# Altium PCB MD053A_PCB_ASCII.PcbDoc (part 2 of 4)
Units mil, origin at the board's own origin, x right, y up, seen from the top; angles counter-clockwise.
Board outline 3650 x 5180 mil, 4 copper layers (Top Layer, GND Layer, Power Layer, Bottom Layer), stack 58.4 mil thick; 251 components, 138 nets, 532 pads, 1017 vias.
Unrouted connection lines stored in the file: 42.
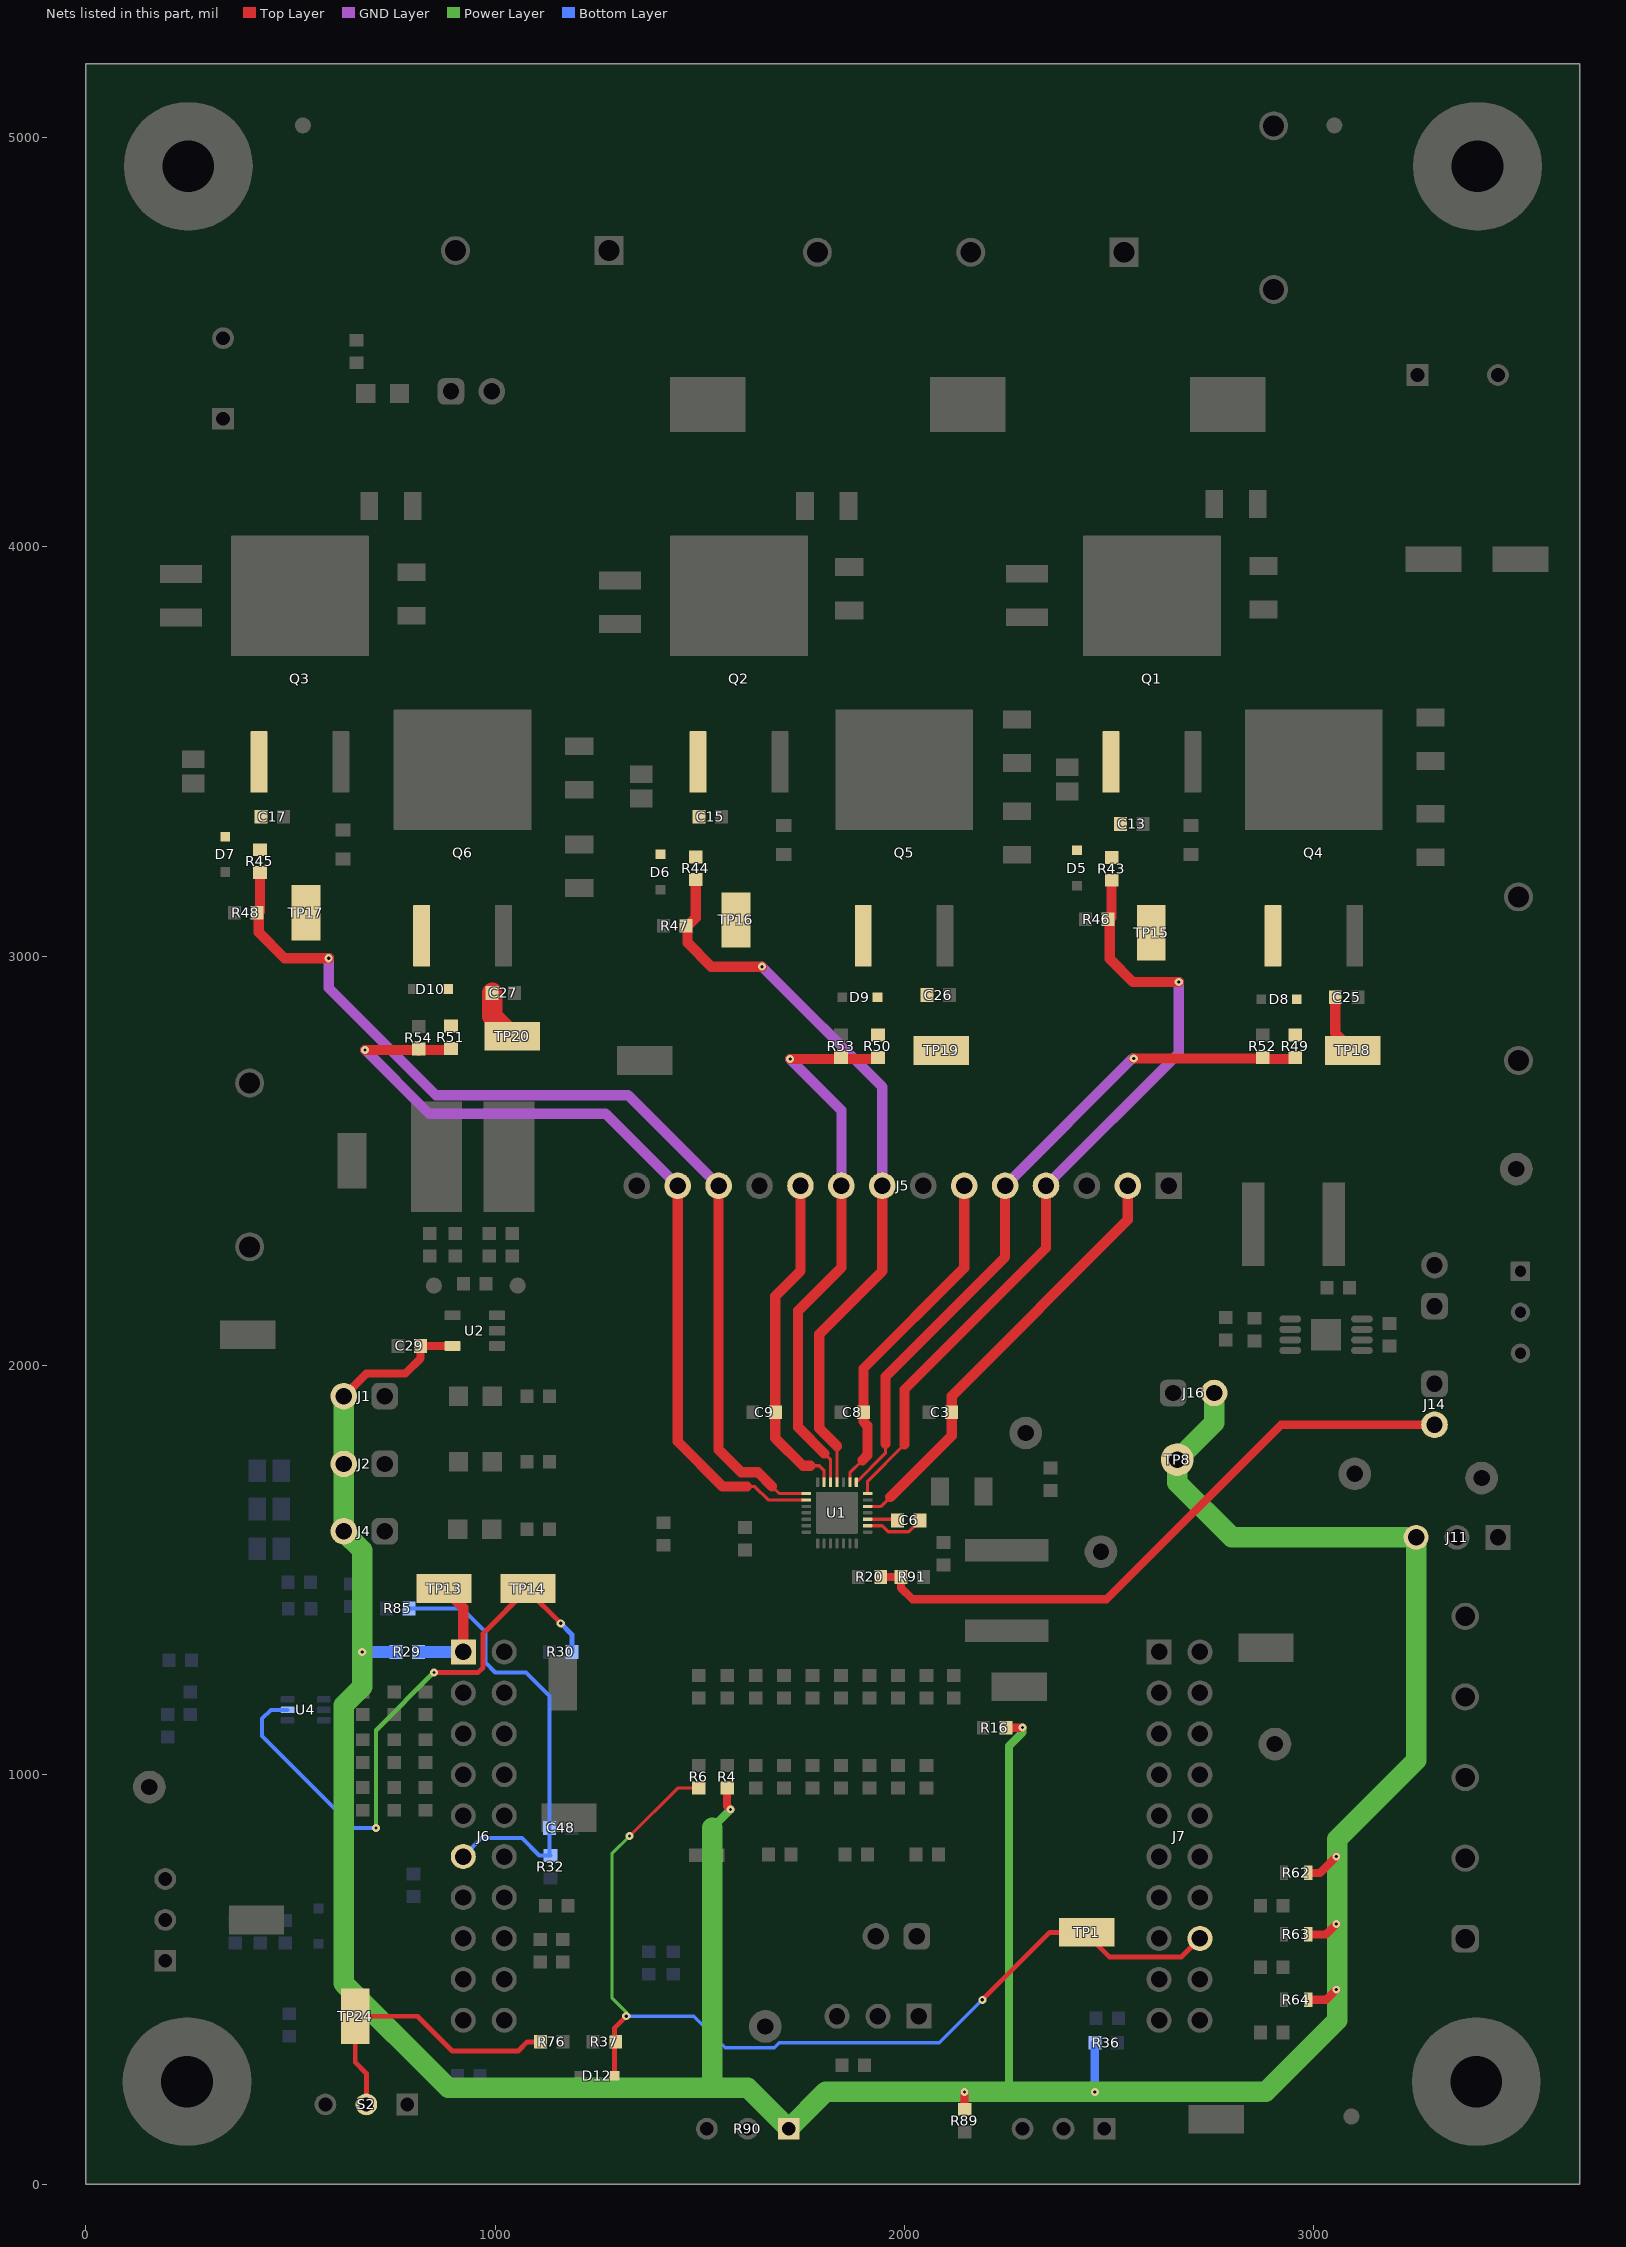
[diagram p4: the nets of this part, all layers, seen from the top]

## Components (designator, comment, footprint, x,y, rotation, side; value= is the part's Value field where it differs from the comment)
C1 "C0603C105K9RACAUTO" 0603L 1610,1577.01 r90 top
C2 "C0603C104K9PAC7867" 0603L 2785,2089.76 r270 top
C3 "C1608X5R1H105K080AB" 0603L 2087.56,1885.43 r180 top
C4 "22201C106MAT2A" 2220_280L 2250,1450 r270 top
C5 "GRM188R72A104KA35J" 0603L 2095,1540 r270 top
C6 "GRM188R71E474KA12D" 0603L 2010,1621.31 r0 top
C7 "UMK316BBJ106KL-T" 1206_190L 2140,1692.43 r0 top
C8 "C1608X5R1H105K080AB" 0603L 1872.16,1885.43 r180 top
C9 "C1608X5R1H105K080AB" 0603L 1656.76,1885.43 r180 top
C10 "12061C392KAZ2A" 1206L 2877.09,3900 r90 top
C11 "12061C392KAZ2A" 1206L 1865,3897.91 r90 top
C12 "12061C392KAZ2A" 1206L 795,3885 r90 top
C13 "GRM188R71H202KA01D" 0603L 2555.16,3323.01 r0 top
C14 "C1210C225K1RACTU" 1210_210L 2299.25,3881.34 r270 top
C15 "GRM188R71H202KA01D" 0603L 1525,3340.67 r0 top
C16 "C1210C225K1RACTU" 1210_210L 1305,3865 r270 top
C17 "GRM188R71H202KA01D" 0603L 454.93,3340.67 r0 top
C18 "C1210C225K1RACTU" 1210_210L 232.32,3880.75 r270 top
C19 "08051C103JAT2A" 0805L 2397.68,3431.97 r270 top
C20 "08051C103JAT2A" 0805L 1356.8,3415 r270 top
C21 "08051C103JAT2A" 0805L 261.85,3451.65 r270 top
C22 "12061C392KAZ2A" 1206L 2275,3525 r270 top
C23 "12061C392KAZ2A" 1206L 1205,3460 r270 top
C24 "12061C392KAZ2A" 1206L 3285,3530 r270 top
C25 "GRM188R71H202KA01D" 0603L 3080,2900 r0 top
C26 "GRM188R71H202KA01D" 0603L 2082.32,2905 r0 top
C27 "GRM188R71H202KA01D" 0603L 1019.72,2910.32 r0 top
C28 "06031C331KAT2A" 0603L 1041.38,2295 r270 top
C29 "C0603C104J4RACTU" 0603L 790,2047.6 r180 top
C30 "C1608NP01H103J080AA" 0603L 950,2200 r180 top
C31 "GRM188R71C222KA01D" 0603L 1110,570 r90 top
C32 "06031C331KAT2A" 0603L 840,2295 r90 top
C33 "22201C106MAT2A" 2220_280L 2950,2345 r180 top
C34 "GRM188R72A104KA35J" 0603L 3060,2190 r180 top
C35 "C0603C106M9PACTU" 0603L 2855,2087.8 r270 top
C36 "GRM188R72A222KA01D" 0603L 425.93,616.22 r270 bottom
C37 "GRM188R71H202KA01D" 0603L 3185,2075 r270 top
C38 "EMZA800ADA100MF80G" CAPSMT_62_F80 3398.7,3970 r0 top
C39 "EKYB101ELL391MK35S" KYB_1250x3500 335,4411.57 r90 top
C40 "EKYB101ELL391MK35S" KYB_1250x3500 3351.57,4420 r0 top
C41 "06035C104JAT2A" 0603L 800,730 r270 bottom
C42 "885012206034" 0603L 2896.85,680 r180 top
C43 "885012206034" 0603L 2896.85,530 r180 top
C44 "885012206034" 0603L 2896.85,370 r180 top
C45 "06035C104JAT2A" 0603L 829.77,1175 r270 top
C46 "06035C104JAT2A" 0603L 829.77,1057.93 r90 top
C47 "06035C104JAT2A" 0603L 829.77,940.86 r90 top
C48 "0603ZC100KAT2A" 0603L 1160,870 r0 bottom
C49 "C0603C105K9RACAUTO" 0603L 1410.85,1588.28 r90 top
D1 "LTST-C170KGKT" LTST-C170KGKT_Green 951.34,1925 r0 top
D2 "LTST-C170KRKT" LED_LTST-C170_Red 951.34,1765 r0 top
D3 "LTST-C170KGKT" LTST-C170KGKT_Green 724.65,4375 r180 top
D4 "LTST-C170KFKT" LTST-C170KFKT_Orange 950,1600 r0 top
D5 "1N4448WX-TP" SOD-323 2421.3,3215.43 r90 top
D6 "1N4448WX-TP" SOD-323 1403.58,3205.59 r90 top
D7 "1N4448WX-TP" SOD-323 340.59,3248.9 r90 top
D8 "1N4448WX-TP" SOD-323 2915,2895 r0 top
D9 "1N4448WX-TP" SOD-323 1890.8,2900 r0 top
D10 "1N4448WX-TP" SOD-323 841.57,2919.83 r0 top
D11 "SZMM3Z3V3ST1G" SOD-323 568.19,630 r90 bottom
D12 "SZMM3Z3V3ST1G" SOD-323 1248.22,264.71 r180 top
FID1 "Fiducial" Fiducial10-20 3050,5030 r0 top
FID2 "Fiducial" Fiducial10-20 530,5030 r0 top
FID3 "Fiducial" Fiducial10-20 3091.85,165 r0 top
H1 "NY PMS 440 0025 PH" "NY PMS 440 0025 PH" 250,4930 r0 top
H2 "NY PMS 440 0025 PH" "NY PMS 440 0025 PH" 3400,4930 r0 top
H3 "NY PMS 440 0025 PH" "NY PMS 440 0025 PH" 3396.85,250 r0 top
H4 "NY PMS 440 0025 PH" "NY PMS 440 0025 PH" 246.85,250 r0 top
H5 "1902C" Keystone_1902C 250.36,4930 r180 bottom
H6 "1902C" Keystone_1902C 3400.36,4930 r180 bottom
H7 "1902C" Keystone_1902C 3396.85,250 r180 bottom
H8 "1902C" Keystone_1902C 246.85,250 r180 bottom
J1 "TSW-102-07-G-S" TSW-102-07-G-S 680,1925 r180 top
J2 "TSW-102-07-G-S" TSW-102-07-G-S 680,1759.41 r180 top
J3 "TSW-102-07-G-S" TSW-102-07-G-S 941.77,4380 r0 top
J4 "TSW-102-07-G-S" TSW-102-07-G-S 680,1595 r180 top
J5 "TSW-114-07-G-S" TSW-114-07-G-S 1995.67,2438.91 r180 top
J6 "SSQ-110-03-G-D" Samtec_SSQ-110-03-x-D 971.85,850 r270 bottom
J7 "SSQ-110-03-G-D" Samtec_SSQ-110-03-x-D 2671.85,850 r270 bottom
J8 "LDO_EN" TSW-102-07-G-S 3295,2195 r90 top
J9 "PVDD_IN" Phoenix_1902547 1090,4846 r180 top
J10 "HALL IN" Phoenix_1792892 3370,993.15 r90 top
J11 "HALL_PWR_SEL" FCI_68001-403HLF 3350,1580 r180 top
J12 "MOTOR_OUT" Phoenix_1904150 2161.8,4842.05 r180 top
J13 "VDS_DISABLE" TSW-102-07-G-S 1980,605 r180 top
J14 "TSW-102-07-G-S" TSW-102-07-G-S 3295,1905 r270 top
J15 "VDSLVL_SEL" FCI_68001-403HLF 1935,410 r180 top
J16 "LDO_OUT" TSW-102-07-G-S 2706.37,1932.76 r0 top
LBL1 "THT-14-423-10" Label_650x200 2403.39,2200.6 r0 top
Logo1 "CE Mark" CE_Mark_5mm 1565.65,613.45 r0 top
Logo2 "Texas Instruments" TI_Stacked_Overlay_Small 1608.01,2198.78 r0 top
Logo3 "FCC disclaimer" FCC_disclaimer 2208,2550 r180 bottom
Logo4 "WEEE logo" WEEE_Minimum 156.74,2140 r0 top
LOGO5 "CAUTION HOT SURFACE" IEC_HotSurface_Small 1075,4120 r0 top
LOGO6 "CAUTION HOT SURFACE" IEC_HotSurface_Small 2065,4092 r0 top
LOGO7 "CAUTION HOT SURFACE" IEC_HotSurface_Small 3076.02,4052 r0 top
NT1 "Net-Tie" NetTie_0603 2700,3283.5 r90 top net-tie
NT2 "Net-Tie" NetTie_0603 1704.76,3284.33 r90 top net-tie
NT3 "Net-Tie" NetTie_0603 627.77,3272.52 r90 top net-tie
Q1 "CSD18536KTTT" KTT0002A-MFG 2604.37,3780 r0 top
Q2 "CSD18536KTTT" KTT0002A-MFG 1595.51,3780 r0 top
Q3 "CSD18536KTTT" KTT0002A-MFG 522.68,3780 r0 top
Q4 "CSD18536KTTT" KTT0002A-MFG 3000,3355 r0 top
Q5 "CSD18536KTTT" KTT0002A-MFG 1999.05,3355 r0 top
Q6 "CSD18536KTTT" KTT0002A-MFG 920,3355.31 r0 top
R1 "ERJ-3GEY0R00V" 0603L 1984.06,995 r90 top
R2 "ERJ-3GEY0R00V" 0603L 1636.11,995 r90 top
R3 "ERJ-3GEY0R00V" 0603L 1844.88,995 r90 top
R4 "ERJ-3GEY0R00V" 0603L 1566.52,995 r90 top
R5 "ERJ-3GEY0R00V" 0603L 1775.29,995 r90 top
R6 "ERJ-3GEY0R00V" 0603L 1496.93,995 r90 top
R7 "ERJ-3GEY0R00V" 0603L 1705.7,995 r90 top
R8 "ERJ-3GEY0R00V" 0603L 1914.47,995 r90 top
R9 "ERJ-3GEY0R00V" 0603L 2120.5,1215 r90 top
R10 "ERJ-3GEY0R00V" 0603L 2053.65,995 r90 top
R11 "ERJ-3GEY0R00V" 0603L 1984.06,1215 r90 top
R12 "ERJ-3GEY0R00V" 0603L 1636.11,1215 r90 top
R13 "ERJ-3GEY0R00V" 0603L 1844.88,1215 r90 top
R14 "ERJ-3GEY0R00V" 0603L 1566.52,1215 r90 top
R15 "ERJ-3GEY0R00V" 0603L 1775.29,1215 r90 top
R16 "CRCW06035K10JNEA" 0603L 2220,1115 r180 top
R17 "ERJ-3GEY0R00V" 0603L 1496.93,1215 r90 top
R18 "ERJ-3GEY0R00V" 0603L 1705.7,1215 r90 top
R19 "ERJ-3GEY0R00V" 0603L 1914.47,1215 r90 top
R20 "ERJ-3GEY0R00V" 0603L 1914.47,1483.21 r180 top
R21 "ERJ-3GEY0R00V" 0603L 2053.65,1215 r90 top
R22 "RC0603JR-07820RL" 0603L 1105,1925 r180 top
R23 "RC0603JR-07820RL" 0603L 1105,1765 r180 top
R24 "RG1608P-202-B-T5" 0603L 661,4477.44 r270 top
R25 "RC0603JR-07820RL" 0603L 1105,1600 r180 top
R26 "ERJ-3GEY0R00V" 0603L 1695.51,805 r0 top
R27 "ERJ-3GEY0R00V" 0603L 1516.93,803.25 r180 top
R28 "ERJ-3GEY0R00V" 0603L 1874.75,290 r0 top
R29 "ERJ-3GEY0R00V" 0603L 785,1300 r0 bottom
R30 "ERJ-3GEY0R00V" 0603L 1160,1300 r0 bottom
R31 "ERJ-3GEY0R00V" 0603L 2055.25,805.11 r0 top
R32 "ERJ-3GEY0R00V" 0603L 1135,775 r90 bottom
R33 "ERJ-3GEY0R00V" 0603L 1881.82,805.11 r180 top
R34 "ERJ-3GEY0R00V" 0603L 1435,540 r90 bottom
R35 "ERJ-3GEY0R00V" 0603L 1150,680 r180 top
R36 "ERJ-3GEY0R00V" 0603L 2493.27,345 r0 bottom
R37 "CRCW060310K0JNEA" 0603L 1266.81,347.4 r180 top
R38 "ERJ-3GEY0R00V" 0603L 2495,405 r0 bottom
R39 "ERJ-3GEY0R00V" 0603L 1375,540 r90 bottom
R40 "CRCW12061R50FKEA" 1206L 2810,4105 r0 top
R41 "CRCW12061R50FKEA" 1206L 1810,4100 r0 top
R42 "CRCW12061R50FKEA" 1206L 745,4100 r0 top
R43 "CRCW060310R0JNEA" 0603L 2505.94,3213.19 r90 top
R44 "CRCW060310R0JNEA" 0603L 1490,3215 r90 top
R45 "CRCW060310R0JNEA" 0603L 425,3232.52 r90 top
R46 "CRCW060310R0JNEA" 0603L 2470,3090 r180 top
R47 "CRCW060310R0JNEA" 0603L 1438.45,3074.13 r180 top
R48 "CRCW060310R0JNEA" 0603L 390.42,3106.39 r180 top
R49 "CRCW060310R0JNEA" 0603L 2955,2780 r90 top
R50 "CRCW060310R0JNEA" 0603L 1935,2780 r90 top
R51 "CRCW060310R0JNEA" 0603L 891.77,2802.05 r90 top
R52 "CRCW060310R0JNEA" 0603L 2875,2780 r90 top
R53 "CRCW060310R0JNEA" 0603L 1845,2780 r90 top
R54 "CRCW060310R0JNEA" 0603L 813.03,2801.12 r90 top
R55 "CRCW12061R50FKEA" 1206L 3285,3295 r90 top
R56 "CRCW12061R50FKEA" 1206L 2275,3300.88 r90 top
R57 "CRCW12061R50FKEA" 1206L 1205,3220 r90 top
R58 "ERJ-3GEY0R00V" 0603L 985,2295 r90 top
R59 "CRCW060356R0JNEA" 0603L 1165,570 r90 top
R60 "CSS2725FT1L00" CSS2725_001 945,2510 r0 top
R61 "ERJ-3GEY0R00V" 0603L 902.6,2295 r90 top
R62 "TNPW060310K0BEEA" TNPW0603 2956.85,760 r0 top
R63 "TNPW060310K0BEEA" TNPW0603 2956.85,610 r0 top
R64 "TNPW060310K0BEEA" TNPW0603 2956.85,450 r0 top
R65 "CRCW0603110KFKEA" 0603L 230,1280 r180 bottom
R66 "CRCW06034K99FKEA" 0603L 255,1175 r90 bottom
R67 "CRCW0603110KFKEA" 0603L 676.39,1175 r90 top
R68 "CRCW0603110KFKEA" 0603L 676.39,1057.93 r90 top
R69 "CRCW0603110KFKEA" 0603L 676.39,940.86 r90 top
R70 "CRCW06034K99FKEA" 0603L 753.08,1175 r270 top
R71 "CRCW06034K99FKEA" 0603L 753.08,1057.93 r270 top
R72 "CRCW06034K99FKEA" 0603L 753.08,940.86 r270 top
R73 "ERA-3ARW103V" 0603L 200,1120 r90 bottom
R74 "ERA-3ARW103V" 0603L 935,264.71 r0 bottom
R75 "ERJ-3GEY0R00V" 0603L 486.85,616.22 r270 bottom
R76 "ERJ-3GEY0R00V" 0603L 1138.27,347.4 r0 top
R77 "ERA-3ARW103V" 0603L 365,616.22 r90 bottom
R78 "RP73PF2A1K0BTDF" 0805L 447.85,1552.3 r0 bottom
R80 "ERJ-3GEY0R00V" 0603L 496.85,388.5 r270 bottom
R81 "ERJ-3GEY0R00V" 0603L 521.14,1470 r0 bottom
R82 "RP73PF2A1K0BTDF" 0805L 447.85,1649.36 r0 bottom
R83 "CRCW0603110KFKEA" 0603L 646.85,1438.24 r90 bottom
R84 "RP73PF2A1K0BTDF" 0805L 447.85,1742.3 r0 bottom
R85 "ERJ-3GEY0R00V" 0603L 761.85,1406.31 r0 bottom
R86 "CRCW06034K99FKEA" 0603L 521.85,1405.72 r0 bottom
R87 "CRCW0603100KJNEA" 0603L 2356.76,1721.91 r270 top
R88 "3296W-1-504LF" FP-3296W-1-504LF_PTH_Potentiometer_9MM53_4MM83-MFG 3505,2130 r90 top
R89 "RC0603JR-077K5L" 0603L 2146.85,155 r90 top
R90 "3352T-1-253LF" Bourns_3352T 1616.93,135 r180 top
R91 "CRCW060310K0JNEA" 0603L 2019.06,1483.21 r180 top
R92 "3352T-1-253LF" Bourns_3352T 2388.35,135 r180 top
S1 "nSLEEP_SW" SW_B12AP 154.33,645.28 r180 top
S2 "DRVOFF_SW" SW_B12AP 685,155 r270 top
SH-J1 "SNT-100-BK-G" SNT-100-BK-G 680,1925 r180 top
SH-J2 "SNT-100-BK-G" SNT-100-BK-G 682,1759.41 r180 top
SH-J3 "SNT-100-BK-G" SNT-100-BK-G 941,4380 r180 top
SH-J4 "SNT-100-BK-G" SNT-100-BK-G 680,1595 r180 top
SH-J5 "SNT-100-BK-G" SNT-100-BK-G 3295,2195 r90 top
SH-J6 "SNT-100-BK-G" SNT-100-BK-G 3292.4,1585 r180 top
SH-J7 "SNT-100-BK-G" SNT-100-BK-G 3295,1905 r90 top
SH-J8 "SNT-100-BK-G" SNT-100-BK-G 1990.84,411.73 r180 top
SH-J9 "SNT-100-BK-G" SNT-100-BK-G 2705,1930 r180 top
TP1 "DRVOFF" Testpoint_Keystone_Miniature 2445,615 r0 top
TP2 "nSLEEP" Testpoint_Keystone_Miniature 1180,895 r0 top
TP3 "LSS" Testpoint_Keystone_Miniature 1365,2745 r0 top
TP4 "nFAULT" Testpoint_Keystone_Miniature 2280,1215 r0 top
TP5 "GND" Testpoint_Keystone_Miniature 1165,1225 r90 top
TP6 "GND" Testpoint_Keystone_Miniature 2761.44,158.56 r180 top
TP7 "GND" Testpoint_Keystone_Miniature 2883.09,1310 r0 top
TP8 "AVDD" Keystone5000 2666.44,1770 r90 top
TP9 "GND" Testpoint_Keystone_Miniature 395,2075 r180 top
TP10 "GND" Testpoint_Keystone_Miniature 650,2500 r90 top
TP11 "PVDD" Keystone5000 2480,1545 r90 top
TP12 "GVDD" Keystone5000 2296.09,1835 r90 top
TP13 "3V3_MCU" Testpoint_Keystone_Miniature 875,1455 r180 top
TP14 "5V" Testpoint_Keystone_Miniature 1080,1455 r0 top
TP15 "GHA_FET" Testpoint_Keystone_Miniature 2602.4,3057.01 r270 top
TP16 "GHB_FET" Testpoint_Keystone_Miniature 1588.09,3088.66 r90 top
TP17 "GHC_FET" Testpoint_Keystone_Miniature 537.44,3106.39 r270 top
TP18 "GLA_FET" Testpoint_Keystone_Miniature 3095,2769.62 r0 top
TP19 "GLB_FET" Testpoint_Keystone_Miniature 2090,2769.62 r180 top
TP20 "GLC_FET" Testpoint_Keystone_Miniature 1041.38,2804.02 r180 top
TP21 "HALL_PWR" Keystone5000 3100,1735 r90 top
TP22 "GND" Keystone5001 2905,1075 r90 top
TP23 "nSLEEP_SW" Testpoint_Keystone_Miniature 416.85,645 r0 top
TP24 "INHA" Testpoint_Keystone_Miniature 657.85,410 r90 top
TP25 "GND" Harwin_D3082-05 3500,2945 r90 top
TP26 "GND" Harwin_D3082-05 400,2490 r270 top
TP27 "GND" Harwin_D3082-05 2902,4829 r90 top
TP28 "GND" Keystone5001 3495,2480 r90 top
TP29 "GND" Keystone5001 155,970 r90 top
TP30 "EXT_VDSLVL" Keystone5000 1660,385 r90 top
TP31 "EXT_HALL_PWR" Keystone5000 3410,1725 r90 top
TP32 "SP" TP_SM_1MM 1054.88,2195 r90 top
TP33 "SN" TP_SM_1MM 850,2195 r90 top
TP34 "OUTA" Testpoint_Keystone_Compact 2790,4347.89 r0 top
TP35 "OUTA" Testpoint_Keystone_Compact 2154.56,4347.89 r0 top
TP36 "OUTA" Testpoint_Keystone_Compact 1519.12,4347.89 r0 top
U1 "DRV8328ARUYR" RUY0028A-MFG 1835,1640 r180 top
U2 "INA180A1IDBVR" DBV0005A_N 950,2085 r180 top
U3 "TPS7A1633QDGNRQ1" DGN0008B_N 3030,2075 r0 top
U4 "TPD4S009DCKR" DCK0006A_N 536.85,1158.5 r180 bottom
ZZ1 "This Assembly Note is for PCB labels only" AssemblyNoteLabel 4947.75,2616.47 r90 top
ZZ2 "These assemblies are ESD sensitive, ESD precautions shall be observed." AssemblyNote 4770.59,5096.77 r90 top
ZZ3 "These assemblies must be clean and free from flux and all contaminants. Use of no clean flux is not acceptable." AssemblyNote 4593.42,3551.5 r90 top
ZZ4 "These assemblies must comply with workmanship standards IPC-A-610 Class 2, unless otherwise specified." AssemblyNote 4416.26,3876.31 r90 top

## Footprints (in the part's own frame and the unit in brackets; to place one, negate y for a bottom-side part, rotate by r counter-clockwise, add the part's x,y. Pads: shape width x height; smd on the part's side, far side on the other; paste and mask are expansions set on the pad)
0603L [mm] "0603 from SM-752 data"
  rect 0.8x0.85 smd: 1(-0.7,0) 2(0.7,0)
  silkscreen extent -0.07,-0.33 0.07,0.33
0805L [mm] "0805 from SM-752 data"
  rect 1.1x1.4 smd: 1(-0.75,0) 2(0.75,0)
1206_190L [mm] "1206_190"
  rect 1.1x1.75 smd: 1(-1.35,0) 2(1.35,0)
  silkscreen extent -0.4,-0.77 0.4,0.77
1206L [mm] "1206 from SM-752 data"
  rect 1.1x1.75 smd: 1(-1.35,0) 2(1.35,0)
  silkscreen extent -0.4,-0.77 0.4,0.77
1210_210L [mm] "1210"
  rect 1.1x2.6 smd: 1(-1.35,0) 2(1.35,0)
  silkscreen extent -0.4,-1.2 0.4,1.2
2220_280L [mm] "Chip Capacitor, Body 5.7x5.0mm, IPC High Density"
  rect 1.4x5.2 smd: 1(-2.5,0) 2(2.5,0)
  silkscreen extent -1.4,-2.5 1.4,2.5
AssemblyNote [mil] "Assembly Note"
AssemblyNoteLabel [mil] "Assembly Note for PCB Labels"
Bourns_3352T [mm] "TH, 3-Leads, Body 9.53x8.89mm, Pitch 2.54mm"
  rect 1.35x1.35 hole 0.85: 1(-2.54,0)
  round 1.35 hole 0.85: 2(0,0) 3(2.54,0)
  silkscreen extent -4.44,-2.6 4.44,7.31
CAPSMT_62_F80 [mm] "6.3 x 7.7mm:  Chemi-Con F80"
  rect 3.5x1.6 smd: 1(-2.7,0) 2(2.7,0)
  silkscreen extent -3.36,-3.4 3.44,3.4
CE_Mark_5mm [mil] "Minimum text height for CE Mark"
CSS2725_001 [mm] "STACKPOLE ELECTRONICS"
  rect 3.18x6.86 smd: 1(-2.25,0) 2(2.25,0)
  silkscreen extent -4.13,-3.7 4.13,3.7
DBV0005A_N [mm] "SOT23, 5-Leads, Body 2.9x1.6mm, Pitch 0.95mm, Lead Span 2.8mm, IPC Medium Density"
  rrect17% 1x0.6 smd: 1(-1.375,0.95) 2(-1.375,0) 3(-1.375,-0.95) 4(1.375,-0.95) 5(1.375,0.95)
  silkscreen extent -0.25,-1.55 0.25,1.55
DCK0006A_N [mm] "SOT23, 6-Leads, Body 2x1.3mm, Pitch 0.65mm, Lead Span 2.1mm, IPC Medium Density"
  rrect25% 0.85x0.4 smd: 1(-1.125,0.65) 2(-1.125,0) 3(-1.125,-0.65) 4(1.125,-0.65) 5(1.125,0) 6(1.125,0.65)
  silkscreen extent -1.5,-1.09 0.51,1.09
DGN0008B_N [mm] "TSOP, 8-Leads, Body 3x3mm, Pitch 0.65mm, Thermal Pad 1.92x1.60mm, IPC Medium Density"
  rrect100% 1.35x0.45 smd: 1(-2.225,0.975) 2(-2.225,0.325) 3(-2.225,-0.325) 4(-2.225,-0.975) 5(2.225,-0.975) 6(2.225,-0.325) 7(2.225,0.325) 8(2.225,0.975)
  rrect5% 1.88x1.98 smd: 9(0,0)
  silkscreen extent -2.7,-1.55 0.95,1.55
FCC_disclaimer [mil]
FCI_68001-403HLF [mm] "Header, 2.54mm, 3x1, TH"
  rect 1.55x1.55 hole 1.02: 1(-2.54,0)
  round 1.55 hole 1.02: 2(0,0) 3(2.54,0)
  silkscreen extent -3.81,-1.21 3.81,1.5
Fiducial10-20 [mm]
  round 1 smd mask+0: 1(0,0)
  Top Layer keep-out circle w1.178: c0,0 r0.5
FP-3296W-1-504LF_PTH_Potentiometer_9MM53_4MM83-MFG [mm]
  rrect8% 1.2x1.2 hole 0.7 paste-1000 mask+0: 1(2.54,0.005)
  round 1.2 hole 0.7 paste-1000 mask+0: 2(0,0.005) 3(-2.54,0.005)
  silkscreen extent -4.89,-2.48 5.77,2.48
Harwin_D3082-05 [mm] "Shorting Plug, 10.16mm spacing, TH"
  round 1.8 hole 1.3: 1(-5.08,0) 2(5.08,0)
  silkscreen extent -3.9,-0.53 3.9,0.53
IEC_HotSurface_Small [mil]
  silkscreen extent -107,-93 107,92
Keystone5000 [mil] "For Keystone 500x miniature loop terminals"
  round 80 hole 40: 1(0,0)
  silkscreen extent -52,-52 52,52
Keystone5001 [mil] "For Keystone 500x miniature loop terminals"
  round 80 hole 40: 1(0,0)
  silkscreen extent -52,-52 52,52
Keystone_1902C [mil] "Hex Standoff, 4-40 threaded, nylon"
  round 1 on Mech4: 0(0,0)
KTT0002A-MFG [mm]
  rrect10% 1.05x3.82 smd paste+0 mask+0: 1(-2.54,-7.755) 3(2.54,-7.755)
  rrect1% 8.55x7.48 smd paste-1000 mask+0: 4(0,2.545)
  silkscreen extent -5.13,-4.62 5.13,4.62
KYB_1250x3500 [mm] "TH, 2-Leads, Dia 12.5mm, Lead Spacing 5mm"
  rect 1.35x1.35 hole 0.85: 1(-2.5,0)
  round 1.35 hole 0.85: 2(2.5,0)
  silkscreen extent -8,-6.5 6.5,6.5
Label_650x200 [mil] "Thermal Transfer Label"
  round 1 on Mech13: 0(0,0)
  silkscreen extent -325,-100 325,100
LED_LTST-C170_Red [mm] "LITE-ON"
  rect 1.2x1.2 smd: 1(-1.05,0) 2(1.05,0)
  silkscreen extent -1.6,-0.99 2.3,1.01
LTST-C170KFKT_Orange [mm] "LITE-ON"
  rect 1.2x1.2 smd: 1(-1.05,0) 2(1.05,0)
  silkscreen extent -1.6,-1.01 2.29,0.99
LTST-C170KGKT_Green [mm] "LITE-ON"
  rect 1.2x1.2 smd: 1(-1.05,0) 2(1.05,0)
  silkscreen extent -1.6,-1.01 2.31,0.99
NetTie_0603 [mm] "Net Tie 0603 size"
  rect 0.8x0.95 smd paste-1: 1(-0.9,0) 2(0.9,0)
  silkscreen extent -0.1,-0.38 0.1,0.38
"NY PMS 440 0025 PH" [mm] "4-40 nylon screw and mounting hole"
  round 8 hole 3.2: 1(0,0)
Phoenix_1792892 [mm] "Terminal Block, 5mm, 5x1, R/A, TH"
  rrect50% 1.7x1.7 hole 1.2: 1(-10,0)
  round 1.7 hole 1.2: 2(-5,0) 3(0,0) 4(5,0) 5(10,0)
  silkscreen extent -12.8,-4.95 12.5,5.55
Phoenix_1902547 [mm] "TH, 2-Leads, Body 19.04x16mm, Pitch 9.52mm"
  rect 1.8x1.8 hole 1.3: 1(-4.76,3.1)
  round 1.8 hole 1.3: 2(4.76,3.1)
  silkscreen extent -10,-8 10.09,8
Phoenix_1904150 [mm] "TH, 3-Leads, Body 28.56x16mm, Pitch 9.52mm"
  rect 1.8x1.8 hole 1.3: 1(-9.52,3.1)
  round 1.8 hole 1.3: 2(0,3.1) 3(9.52,3.1)
  silkscreen extent -14.8,-8 14.85,8
RUY0028A-MFG [mm]
  rrect50% 0.6x0.2 smd paste+0 mask+0: 1(-1.9,1.2) 2(-1.9,0.8) 3(-1.9,0.4) 4(-1.9,0) 5(-1.9,-0.4) 6(-1.9,-0.8) 7(-1.9,-1.2) 15(1.9,-1.2) 16(1.9,-0.8) 17(1.9,-0.4) 18(1.9,0) 19(1.9,0.4) 20(1.9,0.8) 21(1.9,1.2)
  rrect50% 0.2x0.6 smd paste+0 mask+0: 8(-1.2,-1.9) 9(-0.8,-1.9) 10(-0.4,-1.9) 11(0,-1.9) 12(0.4,-1.9) 13(0.8,-1.9) 14(1.2,-1.9) 22(1.2,1.9) 23(0.8,1.9) 24(0.4,1.9) 25(0,1.9) 26(-0.4,1.9) 27(-0.8,1.9) 28(-1.2,1.9)
  rrect5% 2.6x2.6 smd paste-1000 mask+0: 29(0,0)
  silkscreen extent -2.88,-2.05 2.05,2.05
Samtec_SSQ-110-03-x-D [mm] "Receptacle, 2.54mm, 10x2, TH"
  rect 1.55x1.55 hole 1.02: 1(-11.43,1.27)
  round 1.55 hole 1.02: 2(-11.43,-1.27) 3(-8.89,1.27) 4(-8.89,-1.27) 5(-6.35,1.27) 6(-6.35,-1.27) 7(-3.81,1.27) 8(-3.81,-1.27) 9(-1.27,1.27) 10(-1.27,-1.27) 11(1.27,1.27) 12(1.27,-1.27) 13(3.81,1.27) 14(3.81,-1.27) 15(6.35,1.27) 16(6.35,-1.27) 17(8.89,1.27) 18(8.89,-1.27) 19(11.43,1.27) 20(11.43,-1.27)
  silkscreen extent -12.95,-2.48 12.95,3
SNT-100-BK-G [mil] "Samtec STEP model"
  round 1 on Mech3: 0(0,0)
SOD-323 [mm] "NXP recommended land pattern"
  rect 0.6x0.6 smd paste-0.05: 1(-1.1,0) 2(1.1,0)
  silkscreen extent -2.14,-0.86 1.53,0.87
SW_B12AP [mm] "NKK Switches"
  rect 1.35x1.35 hole 0.85 paste+0: 1(-1,2.54)
  round 1.35 hole 0.85 paste+0: 2(-1,0) 3(-1,-2.54)
  silkscreen extent -4.27,-4.4 3.4,4.4
Testpoint_Keystone_Compact [mil] "Compact SMT test point"
  rect 185x135 smd: 1(0,0)
  silkscreen extent -110,-80 110,80
Testpoint_Keystone_Miniature [mil] "Miniature SMT test point"
  rect 135x70 smd: 1(0,0)
  silkscreen extent -78,-46 78,45
TI_Stacked_Overlay_Small [mil]
TNPW0603 [mm] "Vishay"
  rect 0.5x0.9 smd: 1(-0.75,0) 2(0.75,0)
  silkscreen extent -0.2,-0.6 0.2,0.6
TP_SM_1MM [mm] "1mm Test Point, SMT"
  round 1 smd paste-0.5: 1(0,0)
TSW-102-07-G-S [mm] "Samtec 100mil, 1x2, 230 mil above insulator"
  rrect50% 1.65x1.65 hole 1.016: 1(-1.27,0)
  round 1.65 hole 1.016: 2(1.27,0)
  silkscreen extent -2.54,-1.27 2.54,2.12
TSW-114-07-G-S [mm] "Samtec 100mil, 1x14, 230 mil above insulator"
  rrect6% 1.65x1.65 hole 1.016: 1(-16.51,0)
  round 1.65 hole 1.016: 2(-13.97,0) 3(-11.43,0) 4(-8.89,0) 5(-6.35,0) 6(-3.81,0) 7(-1.27,0) 8(1.27,0) 9(3.81,0) 10(6.35,0) 11(8.89,0) 12(11.43,0) 13(13.97,0) 14(16.51,0)
  silkscreen extent -17.78,-1.27 17.78,1.65
WEEE_Minimum [mil] "WEEElie bin"
  silkscreen extent 22,-71 54,74

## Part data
C1 C49: library part CMP-0086190-1, "CAP, CERM, 1 µF, 6.3 V,+/- 10%, X7R, AEC-Q200 Grade 1, 0603"
C2: library part CMP-0085846-1, "CAP, CERM, 0.1 µF, 6.3 V,+/- 10%, X5R, 0603"
C3 C8 C9: library part CMP-0007011-4, "CAP, CERM, 1 uF, 50 V, +/- 10%, X5R, 0603"
C4 C33: library part CMP-0009304-2, "CAP, CERM, 10 uF, 100 V, +/- 20%, X7R, 2220"
C5 C34: library part CMP-0007470-5, "CAP, CERM, 0.1 uF, 100 V, +/- 10%, X7R, 0603"
C6: library part CMP-0007424-3, "CAP, CERM, 0.47 uF, 25 V, +/- 10%, X7R, 0603"
C7: library part CMP-0086153-1, "CAP, CERM, 10 µF, 50 V,+/- 10%, X5R, 1206"
C10 C11 C12 C22 C23 C24: library part CMP-0008756-2, "CAP CER 3900PF 100V X7R 1206"
C13 C15 C17 C25 C26 C27 C37: library part CMP-0007441-5, "CAP, CERM, 2000 pF, 50 V, +/- 10%, X7R, 0603"
C14 C16 C18: library part CMP-0009084-1, "CAP, CERM, 2.2 uF, 100 V, +/- 10%, X7R, 1210"
C19 C20 C21: library part CMP-0007542-2, "CAP, CERM, 0.01 uF, 100 V, +/- 5%, X7R, 0805"
C28 C32: library part CMP-0006740-4, "CAP, CERM, 330 pF, 100 V, +/- 10%, X7R, 0603"
C29: library part CMP-0006857-4, "CAP, CERM, 0.1 uF, 16 V, +/- 5%, X7R, 0603"
C30: library part CMP-0006998-4, "CAP, CERM, 0.01 uF, 50 V, +/- 5%, C0G/NP0, 0603"
C31: library part CMP-0007387-4, "CAP, CERM, 2200 pF, 16 V, +/- 10%, X7R, 0603"
C35: library part CMP-0006872-5, "CAP, CERM, 10 uF, 6.3 V, +/- 20%, X5R, 0603"
C36: library part CMP-0007475-4, "CAP, CERM, 2200 pF, 100 V, +/- 10%, X7R, 0603"
C38: library part CMP-0011397-2, "CAP, AL, 10 uF, 80 V, +/- 20%, 2.4 ohm, SMD"
C39 C40: library part CMP-0009875-2, "CAP, AL, 390 uF, 100 V, +/- 20%, 0.026 ohm, TH"
C41 C45 C46 C47: library part CMP-0083854-1, "CAP, CERM, 0.1 µF, 50 V,+/- 5%, X7R, 0603"
C42 C43 C44: library part CMP-0006826-4, "CAP, CERM, 1000 pF, 16 V, +/- 10%, X7R, 0603"
C48: library part CMP-0006811-4, "CAP, CERM, 10 pF, 10 V, +/- 10%, X7R, 0603"
D1 D3: library part CMP-0002888-2, "LED, Green, SMD"
D2: library part CMP-0002829-3, "LED, Red, SMD"
D4: library part CMP-0002890-1, "LED, Orange, SMD"
D5 D6 D7 D8 D9 D10: library part CMP-0076911-2, "Diode, Switching, 75 V, 0.25 A, SOD-323"
D11 D12: library part CMP-0085730-1, "Diode, Zener, 3.3 V, 300 mW, AEC-Q101, SOD-323"
FID1 FID2 FID3: library part CMP-0077181-1, "Fiducial mark.  There is nothing to buy or mount."
H1 H2 H3 H4: library part CMP-0003617-1, "Machine Screw, Round, #4-40 x 1/4, Nylon, Philips panhead"
H5 H6 H7 H8: library part CMP-0003610-1, "Standoff, Hex, 0.5\"L #4-40 Nylon"
J1 J2 J3 J4 J8 J13 J14 J16: library part CMP-0075405-3, "Header, 100mil, 2x1, Gold, TH"
J5: library part CMP-0075428-1, "Header, 100mil, 14x1, Gold, TH"
J6 J7: library part CMP-0075613-1, "Receptacle, 2.54mm, 10x2, Gold, TH"
J9: library part CMP-0055527-1, "Terminal Block, 9.52mm, 2x1, R/A, TH"
J10: library part CMP-0055532-1, "Terminal Block, 5mm, 5x1, R/A, TH"
J11 J15: library part CMP-0065026-1, "Header, 2.54mm, 3x1, Tin, TH"
J12: library part CMP-0055528-1, "Terminal Block, 9.52mm, 3x1, R/A, TH"
LBL1: library part CMP-0003625-1, "Thermal Transfer Printable Labels, 0.650\" W x 0.200\" H - 10,000 per roll"
Logo1: library part CMP-0074844-1
Logo2: library part CMP-0074838-1, "Texas Instrument Corporate Signature"
Logo3: library part CMP-0074847-1, "FCC_disclaimer"
Logo4: library part CMP-0074769-1
LOGO5 LOGO6 LOGO7: library part CMP-0074837-1, "IEC 61010-1 Hot Surface Warning"
NT1 NT2 NT3: library part CMP-0078142-2, "Single point connection between nets."
Q1 Q2 Q3 Q4 Q5 Q6: library part CMP-0092295-1, "MOSFET 60-V, N channel NexFET power MOSFET, single D2PAK, 1.6 mOhm 3-DDPAK/TO-263 -55 to 175"
R1 R2 R3 R4 R5 R6 R7 R8 R9 R10 R11 R12 R13 R14 R15 R17 R18 R19 R20 R21 R26 R27 R28 R29 R30 R31 R32 R33 R34 R35 R36 R38 R39 R58 R61 R75 R76 R80 R81 R85: library part CMP-0025874-4, "RES, 0, 5%, 0.1 W, AEC-Q200 Grade 0, 0603"
R16: library part CMP-0025830-4, "RES, 5.1 k, 5%, 0.1 W, AEC-Q200 Grade 0, 0603"
R22 R23 R25: library part CMP-0025941-5, "RES, 820, 5%, 0.1 W, 0603"
R24: library part CMP-0023463-3, "RES, 2.00 k, 0.1%, 0.1 W, 0603"
R37: library part CMP-0025701-2, "RES, 10 k, 5%, 0.1 W, 0603"
R40 R41 R42 R55 R56 R57: library part CMP-0016763-3, "RES, 1.50, 1%, 0.25 W, AEC-Q200 Grade 0, 1206"
R43 R44 R45 R46 R47 R48 R49 R50 R51 R52 R53 R54: library part CMP-0025703-4, "RES, 10, 5%, 0.1 W, AEC-Q200 Grade 0, 0603"
R59: library part CMP-0025829-4, "RES, 56, 5%, 0.1 W, AEC-Q200 Grade 0, 0603"
R60: library part CMP-0015025-2, "RES, 0.001, 1%, 4 W, RES_2725"
R62 R63 R64: library part CMP-0025686-1, "RES, 10.0 k, 0.1%, 0.1 W, AEC-Q200 Grade 1, 0603"
R65 R67 R68 R69 R83: library part CMP-0022008-4, "RES, 110 k, 1%, 0.1 W, AEC-Q200 Grade 0, 0603"
R66 R70 R71 R72 R86: library part CMP-0022458-4, "RES, 4.99 k, 1%, 0.1 W, AEC-Q200 Grade 0, 0603"
R73 R74 R77: library part CMP-0086251-1, "RES, 10.0 k, 0.05%, 0.1 W, AEC-Q200 Grade 0, 0603"
R78 R82 R84: library part CMP-0019089-2, "RES, 1.00 k, 0.1%, 0.25 W, 0805"
R87: library part CMP-0025698-4, "RES, 100 k, 5%, 0.1 W, AEC-Q200 Grade 0, 0603"
R88: library part CMP-0088033-1, "500 kOhms 0.5W, 1/2W PC Pins Through Hole Trimmer Potentiometer Cermet 25 Turn Top Adjustment"
R89: library part CMP-0025940-5, "RES, 7.5 k, 5%, 0.1 W, 0603"
R90 R92: library part CMP-0001776-2, "Trimmer Potentiometer, 25kohm, 0.5W, TH"
R91: library part CMP-0025701-3, "RES, 10 k, 5%, 0.1 W, 0603"
S1 S2: library part CMP-0002155-2, "SWITCH TOGGLE SPDT 0.4VA 28V"
SH-J1 SH-J2 SH-J3 SH-J4 SH-J5 SH-J6 SH-J7 SH-J8 SH-J9: library part CMP-0003623-3, "Shunt, 100mil, Gold plated, Black"
TP1 TP2 TP3 TP4 TP5 TP6 TP7 TP9 TP10 TP13 TP14 TP15 TP16 TP17 TP18 TP19 TP20 TP23 TP24: library part CMP-0055152-1, "Test Point, Miniature, SMT"
TP8 TP11 TP12 TP21 TP30 TP31: library part CMP-0055137-1, "Test Point, Miniature, Red, TH"
TP22 TP28 TP29: library part CMP-0055138-1, "Test Point, Miniature, Black, TH"
TP25 TP26 TP27: library part CMP-0075110-1, "1mm Uninsulated Shorting Plug, 10.16mm spacing, TH"
TP32 TP33: library part CMP-0003825-1, "1mm Test Point, SMT"
TP34 TP35 TP36: library part CMP-0055153-1, "Test Point, Compact, SMT"
U1: library part CMP-0091885-1, "Three-Phase BLDC Gate Driver"
U2: library part CMP-0013067-2, "Low- and High-Side Measurement, Multichannel, Voltage Output, Current-Sense Amplifier, DBV0005A (SOT-5)"
U3: library part CMP-0066910-3, "Automotive 60V, 5uA IQ Low-Dropout 100mA Linear Regulator with Enable and Power Good, DGN0008B (VSSOP-8)"
U4: library part CMP-0043118-3, "4-Channel ESD Solution for High-Speed Differential Interface, DCK0006A (SOT-SC70-6)"
ZZ1: library part CMP-0003616-3
ZZ2: library part CMP-0077236-1
ZZ3: library part CMP-0077237-1
ZZ4: library part CMP-0077238-1

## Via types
v1: diameter 20, hole 10, Top Layer to Bottom Layer, tented both sides, 759 vias
v2: diameter 19.68, hole 7.87, Top Layer to Bottom Layer, tented both sides, 248 vias
v3: diameter 19.68, hole 7.87, Top Layer to Bottom Layer, 10 vias

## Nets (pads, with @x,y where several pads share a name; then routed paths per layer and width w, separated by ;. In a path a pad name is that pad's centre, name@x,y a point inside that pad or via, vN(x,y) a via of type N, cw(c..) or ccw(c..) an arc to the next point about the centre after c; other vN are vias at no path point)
3V3_MCU: J6.1 R29.2 TP13.1 | length 283.7
  Top Layer w25: TP13.1@875,1455 921.85,1408.15 J6.1@921.85,1300
  Bottom Layer w30: R29.2@812.56,1300 J6.1@921.85,1300
+5V: R30.2 TP14.1 U4.5 | length 1486.9
  Top Layer w12: v2(850,1250) 958.15,1250 970.24,1262.08 970.24,1345.24 TP14.1@1080,1455 1080,1450 v2(1160,1370)
  Power Layer w10: v2(708.54,870) 708.54,1108.54 710,1110
  Power Layer w12: 710,1110 v2(850,1250)
  Bottom Layer w10: U4.5@492.56,1158.5 451.59,1158.5 430,1136.91 430,1095 655,870 v2(708.54,870)
  Bottom Layer w12: v2(1160,1370) 1187.56,1342.44 R30.2@1187.56,1300
AVDD: C29.1 J1.2 J2.2 J4.2 J11.3 J16.2 R4.1 R16.1 R29.1 R36.1 R62.2 R63.2 R64.2 R89.2 R90.1 TP8.1 U2.5 | length 8830
  Top Layer w20: J1.2@630,1925 685,1980 780,1980 817.56,2017.56 C29.1@817.56,2047.6 U2.5@895.87,2047.6 ; R4.1@1566.52,967.44 1566.52,923.48 v2(1575,915) ; R89.2@2146.85,186.5 v2(2146.85,225) ; R16.1@2247.56,1115 2287.81,1115 v2(2288.35,1115.53) ; R64.2@2986.38,450 3030,450 v2(3055,475) ; R63.2@2986.38,610 3030,610 v2(3055,635) ; R62.2@2986.38,760 3015,760 v2(3055,800)
  Power Layer w20: 985,235 985.12,235 ; 1530,870 v2(1575,915) ; 2255,225 2255,1070 2288.35,1103.35 v2(2288.35,1115.53)
  Power Layer w50: J1.2@630,1925 J2.2@630,1759.41 J4.2@630,1595 630,1593.06 675,1548.06 v2(675,1300) 675,1215 630,1170 630,490 885,235 985,235 ; 985.12,235 1530,235 ; 1530,870 1530,235 ; J16.2@2756.37,1932.76 2756.37,1859.93 TP8.1@2666.44,1770 2666.44,1713.56 2800,1580 J11.3@3250,1580 3250,1035 3057.17,842.17 3057.17,400 2882.17,225 v2(2465,225) 2255,225 v2(2146.85,225) 1806.93,225 R90.1@1716.93,135 1616.93,235 1530,235
  Bottom Layer w20: v2(2465,225) 2465,344.29 R36.1@2465.71,345
  Bottom Layer w30: v2(675,1300) R29.1@757.44,1300
BSTA: C3.1 J5.2 U1.5 | length 1065.8
  Top Layer w7.87: U1.5@1909.8,1655.75 1942.63,1655.75 1965.32,1678.44
  Top Layer w25: 1965.32,1678.44 2115.12,1828.24 C3.1@2115.12,1885.43 2115.12,1925.12 2545.67,2355.67 J5.2@2545.67,2438.91
BSTB: C8.1 J5.6 U1.9 | length 847.7
  Top Layer w7.87: U1.9@1866.5,1714.8 1866.5,1737.78 1897.27,1768.55
  Top Layer w25: 1897.27,1768.55 1909.37,1780.65 1909.37,1853.14 1899.72,1862.8 C8.1@1899.72,1885.43 1899.72,1992.58 2145.67,2238.54 J5.6@2145.67,2438.91
BSTC: C9.1 J5.10 U1.13 | length 821.7
  Top Layer w7.87: 1770,1755 1791.54,1755 1803.5,1743.03 U1.13@1803.5,1714.8
  Top Layer w25: C9.1@1684.32,1885 1684.32,1822.47 1751.79,1755 1770,1755 ; C9.1@1684.32,1885.43 1684.32,2169.32 1745.67,2230.67 J5.10@1745.67,2438.91
CPH: C6.1 U1.3 | length 73.9
  Top Layer w7.87: U1.3@1909.8,1624.25 1979.5,1624.25 C6.1@1982.44,1621.31
CPL: C6.2 U1.2 | length 145.4
  Top Layer w7.87: U1.2@1909.8,1608.5 1945.21,1608.5
  Top Layer w8: 1945.21,1608.5 1960.14,1593.58 2009.83,1593.58 C6.2@2037.56,1621.31
CTAP: C48.1 J6.11 R32.2 R85.2 | length 1115.9
  Bottom Layer w10: R85.2@789.41,1406.31 918.69,1406.31 975.85,1349.15 975.85,1274.15 1000,1250 1075,1250 1132.44,1192.56 C48.1@1132.44,870 1132.44,805.12 R32.2@1135,802.56 1107.44,802.56 1065,845 966.85,845 J6.11@921.85,800
DRVOFF: D12.1 J7.16 R6.1 R37.1 TP1.1 | length 2447.4
  Top Layer w8: D12.1@1291.75,264.71 D12.1@1294.37,267.55 ; v2(1328,850) 1445.44,967.44 R6.1@1496.93,967.44
  Top Layer w12: D12.1@1291.75,264.71 1291.75,344.55 1291.52,381.52 v2(1320,410) ; v2(2190,450) 2355,615 TP1.1@2445,615 2445,610.5 2500.5,555 2676.85,555 J7.16@2721.85,600
  Power Layer w8: v2(1320,410) 1320,420 1285,455 1285,807 v2(1328,850)
  Bottom Layer w8: v2(1320,410) 1485,410 1561.87,333.13 1681.49,333.13 1693.36,345 2085,345 v2(2190,450)
DRVOFF_SW: R76.1 S2.2 TP24.1 | length 724.2
  Top Layer w12: S2.2@685,194.37 685,270 657.85,297.15 TP24.1@657.85,410 810,410 895,325 1055.85,325 1078.25,347.4 R76.1@1110.71,347.4
DT: J14.2 R20.1 R91.2 | length 1562.3
  Top Layer w20: R20.1@1942.03,1483.21 R91.2@1986.2,1483.21 ; R91.2@1991.5,1483.21 1991.5,1456.65 2019.35,1428.8 2493.8,1428.8 2920,1855 J14.2@3295,1855
GHA: J5.4 R43.1 R46.1 U1.7 | length 1946.5
  Top Layer w7.87: U1.7@1909.8,1687.24 1909.8,1717.18 2000,1807.37
  Top Layer w25: 2000,1807.37 2000,1941.39 2345.67,2287.06 J5.4@2345.67,2438.91 ; R43.1@2505.94,3181.69 2505.94,3094.45 2501.5,3090 2501.5,2993.5 2558.19,2936.81 v2(2670,2936.81)
  GND Layer w25: J5.4@2345.67,2438.91 2670,2763.24 v2(2670,2936.81)
GHA_FET: C13.1 D5.2 Q1.1 R43.2 TP15.1
GHB: J5.8 R44.1 R47.1 U1.11 | length 1828.8
  Top Layer w7.87: U1.11@1835,1714.8 1835,1802.61 1835.3,1802.9
  Top Layer w25: R44.1@1490,3183.5 1490,3094.18 1469.95,3074.13 1469.95,3032.41 1527.89,2974.47 v2(1651.87,2974.47) ; 1835.3,1802.9 1791.54,1846.67 1791.54,2076.44 1945.67,2230.58 J5.8@1945.67,2438.91
  GND Layer w25: v2(1651.87,2974.47) 1945.67,2680.67 J5.8@1945.67,2438.91
GHB_FET: C15.1 D6.2 Q2.1 R44.2 TP16.1
GHC: J5.12 R45.1 R48.1 U1.15 | length 2470.5
  Top Layer w7.87: 1675.97,1705 1693.73,1687.24 U1.15@1760.2,1687.24
  Top Layer w25: R45.1@425,3201.02 425,3109.47 421.92,3106.39 421.92,3058.08 485,2995 v2(592.9,2995) ; J5.12@1545.67,2438.91 1545.67,1794.33 1600.98,1739.02 1641.95,1739.02 1675.97,1705
  GND Layer w25: v2(592.9,2995) 592.9,2922.34 855.24,2660 1324.58,2660 J5.12@1545.67,2438.91
GHC_FET: C17.1 D7.2 Q3.1 R45.2 TP17.1
GLA: J5.5 R49.1 R52.1 U1.8 | length 1713.7
  Top Layer w7.87: U1.8@1882.24,1714.8 1882.6,1714.8 1953.41,1785.62 1953.41,1808.01
  Top Layer w25: 1953.41,1808.01 1953.41,1972.85 2245.67,2265.11 J5.5@2245.67,2438.91 ; v2(2560,2750) 2873.5,2750 2875,2748.5 R49.1@2955,2748.5
  GND Layer w25: J5.5@2245.67,2438.91 2556.76,2750 v2(2560,2750)
GLA_FET: C25.1 D8.2 Q4.1 R49.2 TP18.1 | length 148
  Top Layer w25: C25.1@3052.44,2900 3052.44,2812.18 TP18.1@3095,2769.62
GLB: J5.9 R50.1 R53.1 U1.12 | length 1376.6
  Top Layer w7.87: 1803.66,1785 1819.25,1769.41 U1.12@1819.25,1714.8
  Top Layer w25: v2(1720.5,2748.5) R50.1@1935,2748.5 ; 1803.66,1785 1740,1848.66 1740,2133.46 1845.67,2239.14 J5.9@1845.67,2438.91
  GND Layer w25: v2(1720.5,2748.5) 1845.67,2623.34 J5.9@1845.67,2438.91
GLB_FET: C26.1 D9.2 Q5.1 R50.2 TP19.1
GLC: J5.13 R51.1 R54.1 U1.16 | length 2110.7
  Top Layer w7.87: 1614.31,1704 1634.43,1704 1666.93,1671.5 U1.16@1760.2,1671.5
  Top Layer w25: v2(682,2771) 810.41,2771 812.41,2769 813.96,2770.55 R51.1@891.77,2770.55 ; J5.13@1445.67,2438.91 1445.67,1814.33 1556,1704 1614.31,1704
  GND Layer w25: v2(682,2771) 838,2615 1269.58,2615 J5.13@1445.67,2438.91
GLC_FET: C27.1 D10.2 Q6.1 R51.2 TP20.1 | length 126.7
  Top Layer w50: C27.1@992.17,2910.32 992.17,2853.23 TP20.1@1041.38,2804.02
